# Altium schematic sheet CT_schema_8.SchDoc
size 308 x 210 mm
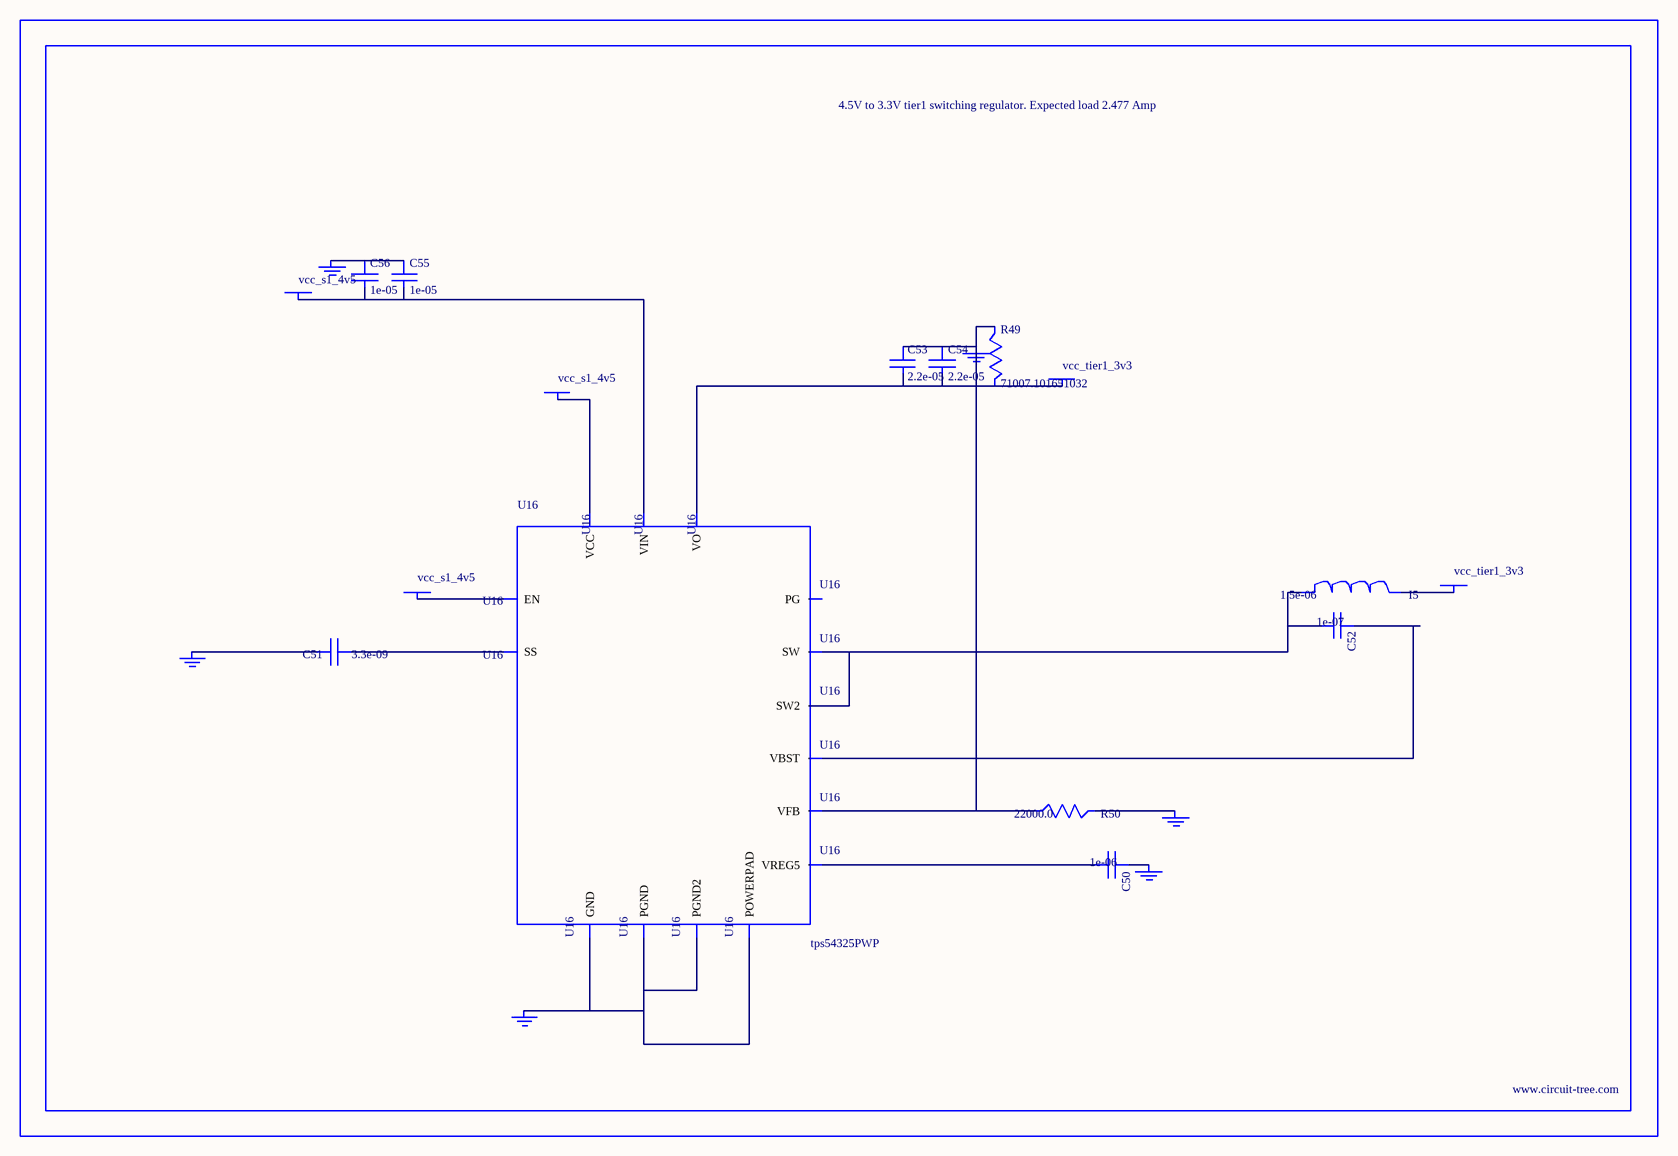
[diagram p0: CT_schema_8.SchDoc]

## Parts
BORDER7  (no value)
C50  1e-06  [C0603]
C51  3.3e-09  [C0402]
C52  1e-07  [C0402]
C53  2.2e-05  [C1210]
C54  2.2e-05  [C1210]
C55  1e-05  [C0805]
C56  1e-05  [C0805]
GND_INSTANCE_7_0  (no value)
GND_INSTANCE_7_1  (no value)
GND_INSTANCE_7_2  (no value)
GND_INSTANCE_7_3  (no value)
GND_INSTANCE_7_4  (no value)
GND_INSTANCE_7_5  (no value)
I5  1.5e-06  [IND_PM3316]
POWER_INSTANCE_7_0  vcc_tier1_3v3
POWER_INSTANCE_7_1  vcc_s1_4v5
POWER_INSTANCE_7_2  vcc_tier1_3v3
POWER_INSTANCE_7_3  vcc_s1_4v5
POWER_INSTANCE_7_4  vcc_s1_4v5
R49  71007.101651032  [R0603]
R50  22000.0  [R0603]
U16  tps54325PWP  [HTSSOP14]

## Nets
NetC50_1: C50.1 GND_INSTANCE_7_2.0(GND)
NetC50_2: C50.2 U16.3(VREG5)
NetC51_1: C51.1 U16.4(SS)
NetC51_2: C51.2 GND_INSTANCE_7_3.0(GND)
NetC52_1: C52.1 U16.12(VBST)
NetC52_2: C52.2 I5.1 U16.10(SW) U16.11(SW2)
NetC53_1: C53.1 C54.1 GND_INSTANCE_7_0.0(GND) R49.1 R50.1 U16.2(VFB)
NetC53_2: C53.2 C54.2 POWER_INSTANCE_7_0.0(PWR) R49.2 U16.1(VO)
NetC55_1: C55.1 C56.1 GND_INSTANCE_7_5.0(GND)
NetC55_2: C55.2 C56.2 POWER_INSTANCE_7_3.0(PWR) U16.13(VIN)
NetGND_INSTANCE_7_1_0: GND_INSTANCE_7_1.0(GND) R50.2
NetGND_INSTANCE_7_4_0: GND_INSTANCE_7_4.0(GND) U16.5(GND) U16.8(PGND) U16.9(PGND2) U16.15(POWERPAD)
NetI5_2: I5.2 POWER_INSTANCE_7_2.0(PWR)
NetPOWER_INSTANCE_7_1_0: POWER_INSTANCE_7_1.0(PWR) U16.7(EN)
NetPOWER_INSTANCE_7_4_0: POWER_INSTANCE_7_4.0(PWR) U16.14(VCC)

Not connected (* = marked no-connect by the designer): U16 6(PG)

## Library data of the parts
BORDER7 = BORDER_PAGE7
C50 = C0603C105K3RACTU
C51 = C0402C332K3RAC
C52 = C0402C104K3RACTU
C53 C54 = GRM32ER61E226ME15L
C55 C56 = C0805C106K8RACTU
GND_INSTANCE_7_0-GND_INSTANCE_7_5 = GND
I5 = PM3316-1R5M-RC
POWER_INSTANCE_7_0-POWER_INSTANCE_7_4 = PWR
R49 = R49
R50 = RC0603JR-0722KL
